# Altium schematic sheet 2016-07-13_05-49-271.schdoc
size 217 x 157 mm; SheetNumber: 1; SheetTotal: 1
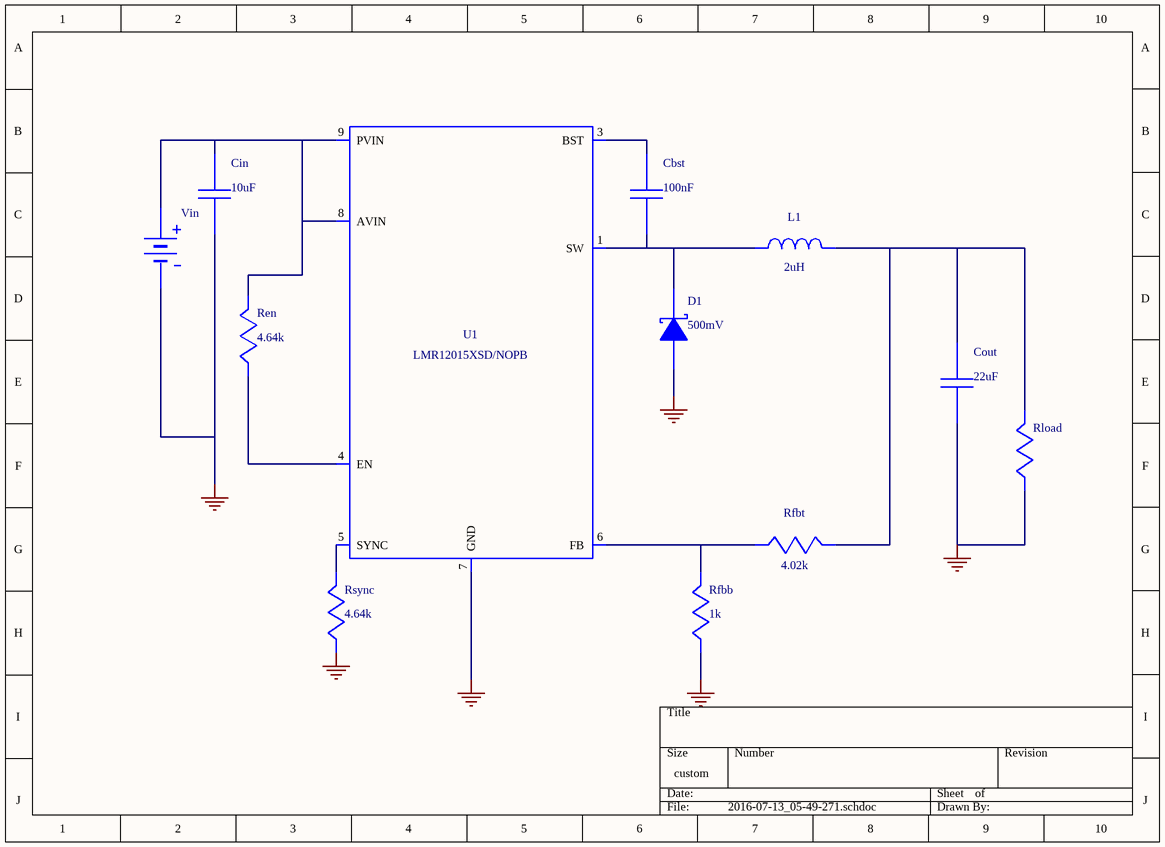
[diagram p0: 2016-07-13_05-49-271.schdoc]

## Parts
Cbst  value 100nF  (hidden comment: GRM188R71C104KA01D)
Cin  value 10uF  (hidden comment: GRM31CR61E106KA12L)
Cout  value 22uF  (hidden comment: GRM31CR61A226KE19L)
D1  value 500mV  (hidden comment: B220-13-F)
L1  value 2uH  (hidden comment: CDR7D28MNNP-2R0NC)
Ren  value 4.64k  (hidden comment: CRCW04024K64FKED)
Rfbb  value 1k  (hidden comment: CRCW06031K00FKEA)
Rfbt  value 4.02k  (hidden comment: CRCW04024K02FKED)
Rload  WB_LOAD_RESISTOR  (value not drawn)
Rsync  value 4.64k  (hidden comment: CRCW04024K64FKED)
U1  LMR12015XSD/NOPB
Vin  WB_BATTERY  (value not drawn)

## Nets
0: Cin.2 Cout.2 D1.2(A) Rfbb.2 Rload.2 Rsync.2 U1.7(GND) U1.11(DAP) Vin.2(-)
NetCbst_1: Cbst.1 U1.3(BST)
NetCbst_2: Cbst.2 D1.1(K) L1.1 U1.1(SW) U1.2(SW)
NetCin_1: Cin.1 Ren.1 U1.8(AVIN) U1.9(PVIN) U1.10(PVIN) Vin.1(+)
NetCout_1: Cout.1 L1.2 Rfbt.1 Rload.1
NetRen_2: Ren.2 U1.4(EN)
NetRfbb_1: Rfbb.1 Rfbt.2 U1.6(FB)
NetRsync_1: Rsync.1 U1.5(SYNC)

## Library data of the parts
Cbst = GRM188R71C104KA01D: GRM188R71C104KA0; Manufacturer Name: MuRata
Cin = GRM31CR61E106KA12L: GRM31CR61E106KA1; Manufacturer Name: MuRata
Cout = GRM31CR61A226KE19L: GRM31CR61A226KE1; Manufacturer Name: MuRata
D1 = B220-13-F: Manufacturer Name: Diodes Inc.
L1 = CDR7D28MNNP-2R0NC: CDR7D28MNNP-2R0N; Manufacturer Name: Sumida
Ren Rsync = CRCW04024K64FKED: Manufacturer Name: Vishay-Dale
Rfbb = CRCW06031K00FKEA: Manufacturer Name: Vishay-Dale
Rfbt = CRCW04024K02FKED: Manufacturer Name: Vishay-Dale
U1 = LMR12015XSD/NOPB: Manufacturer Name: Texas Instruments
